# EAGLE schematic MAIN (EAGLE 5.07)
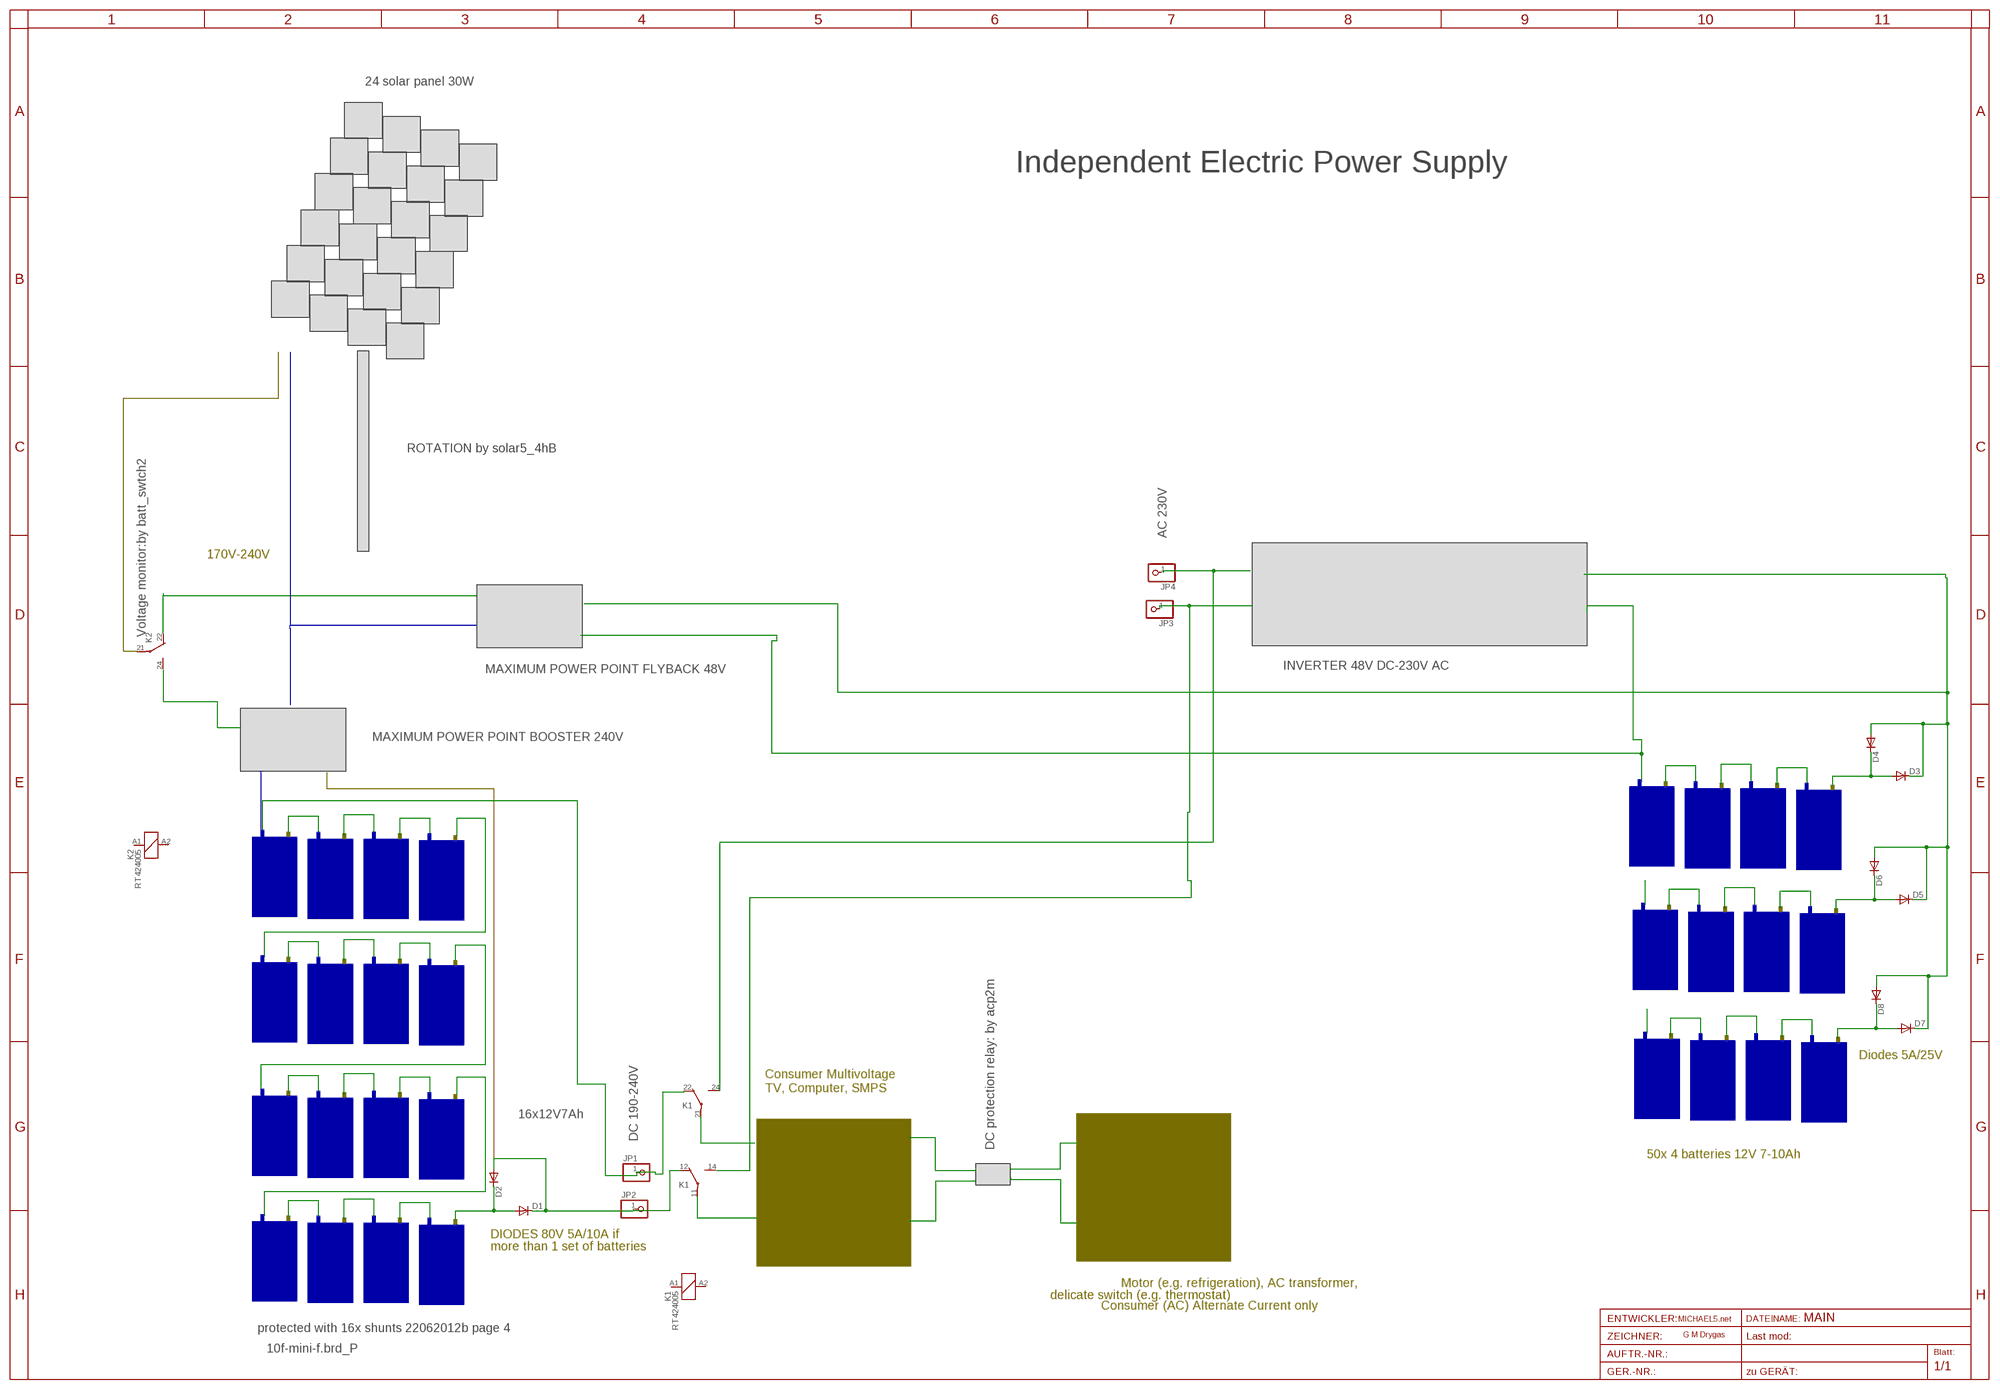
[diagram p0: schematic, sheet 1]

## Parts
D1  DIODE-SMC  [SMC]
D2  DIODE-SMC  [SMC]
D3  DIODE-SMC  [SMC]
D4  DIODE-SMC  [SMC]
D5  DIODE-SMC  [SMC]
D6  DIODE-SMC  [SMC]
D7  DIODE-SMC  [SMC]
D8  DIODE-SMC  [SMC]
JP1  PINHD-1X14.5MM  [1X4MM5]
JP2  PINHD-1X14.5MM  [1X4MM5]
JP3  PINHD-1X14.5MM  [1X4MM5]
JP4  PINHD-1X14.5MM  [1X4MM5]
K1  RT424005  [RT2C/O]
K2  RT424005  [RT2C/O]

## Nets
N$17: D1.C
N$18: D1.A
N$23: D3.C D5.C D7.C
N$24: D3.A
N$30: D5.A
N$36: D7.A
Unconnected: D2.A D2.C D4.A D4.C D6.A D6.C D8.A D8.C JP1.1 JP2.1 JP3.1 JP4.1 K1.11(2:P) K1.12(2:O) K1.14(2:S) K1.21(3:P) K1.22(3:O) K1.24(3:S) K1.A1 K1.A2 K2.11(2:P) K2.12(2:O) K2.14(2:S) K2.21(3:P) K2.22(3:O) K2.24(3:S) K2.A1 K2.A2

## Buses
B$1
B$2

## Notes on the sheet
- 24 solar panel 30W
- Independent Electric Power Supply
- ROTATION by solar5_4hB
- AC 230V
- 170V-240V
- Voltage monitor:by batt_swtch2
- MAXIMUM POWER POINT FLYBACK 48V | INVERTER 48V DC-230V AC
- MAXIMUM POWER POINT BOOSTER 240V
- Diodes 5A/25V
- Consumer Multivoltage
- TV, Computer, SMPS
- 16x12V7Ah
- DC 190-240V
- DC protection relay: by acp2m
- 50x 4 batteries 12V 7-10Ah
- DIODES 80V 5A/10A if
- more than 1 set of batteries
- Motor (e.g. refrigeration), AC transformer,
- delicate switch (e.g. thermostat) | Consumer (AC) Alternate Current only
- MICHAEL5.net
- protected with 16x shunts 22062012b page 4
- G M Drygas
- 10f-mini-f.brd_P

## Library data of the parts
D1-D8 = diode:DIODE-: DIODE
JP1-JP4 = pinhead:PINHD-1X1: PIN HEADER
K1 K2 = relay:RT42?*: Power PCB Relay SCHRACK 2 pole 8 A, DC and AC-coil Source: http://www.schrack.com/.. 5842.pdf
